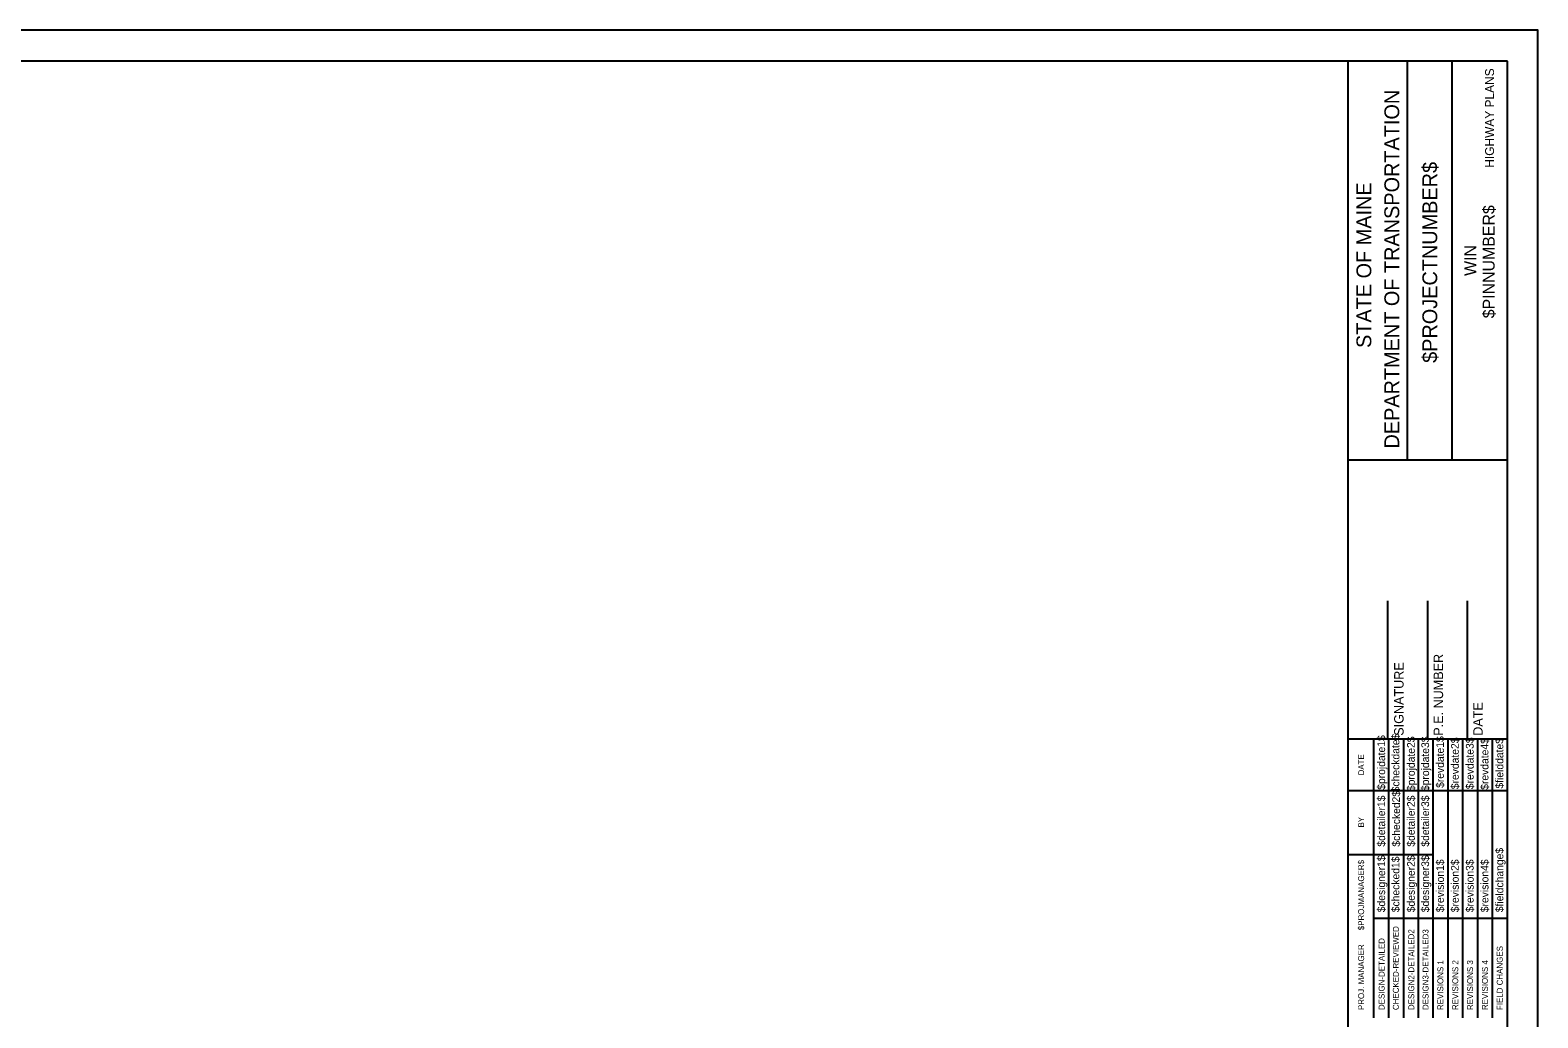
# Model space of a CAD drawing. Extents: x 850598 to 870284, y 366541 to 366651.
# Drawn here: x 857547.6 to 857642.3, y 366589.2 to 366651.2 of the extents above; entities that cross this region are included whole.
import ezdxf

# ---------------------------------------------------------------- set-up
doc = ezdxf.new("R2010")
doc.units = 0
for name, color, linetype in [('BORDER', 7, 'Continuous'), ('HIGHWAY_TITLE', 7, 'Continuous'), ('PLOT BOUNDARY', 7, 'Continuous')]:
    doc.layers.add(name, color=color, linetype=linetype)

msp = doc.modelspace()

# ---------------------------------------------------------------- linework, layer by layer
at = {"layer": 'BORDER'}
for p, q in [((857640.35, 366649.225), (857480.35, 366649.225)), ((857630.35, 366544.225), (857630.35, 366649.225)), ((857634.079, 366624.222), (857634.079, 366649.222)), ((857636.874, 366624.222), (857636.874, 366649.222)), ((857640.35, 366544.225), (857640.35, 366649.225)), ((857630.351, 366624.219), (857640.35, 366624.219)), ((857632.85, 366606.728), (857632.85, 366615.376)), ((857635.35, 366606.728), (857635.35, 366615.376)), ((857637.85, 366606.728), (857637.85, 366615.376)), ((857630.35, 366606.728), (857640.35, 366606.728))]:
    msp.add_line(p, q, dxfattribs=at)
for points in [[(857631.965, 366603.478), (857631.965, 366606.728)], [(857631.966, 366589.231), (857631.966, 366606.022)], [(857632.897, 366589.231), (857632.897, 366606.728)], [(857633.829, 366606.728), (857633.829, 366589.231)], [(857634.761, 366589.231), (857634.761, 366606.728)], [(857635.693, 366589.231), (857635.693, 366606.728)], [(857636.624, 366589.231), (857636.624, 366606.728)], [(857637.556, 366589.231), (857637.556, 366606.728)], [(857638.488, 366589.231), (857638.488, 366606.728)], [(857639.419, 366589.231), (857639.419, 366606.728)], [(857630.35, 366603.478), (857640.35, 366603.478)], [(857630.35, 366599.478), (857631.966, 366599.478)], [(857631.965, 366599.478), (857635.692, 366599.478)], [(857631.965, 366595.478), (857640.35, 366595.478)]]:
    msp.add_lwpolyline(points, dxfattribs=at)
at = {"layer": 'PLOT BOUNDARY'}
msp.add_lwpolyline([(857472.257, 366541.166), (857642.257, 366541.166), (857642.257, 366651.166), (857472.257, 366651.166)], close=True, dxfattribs=at)

# ---------------------------------------------------------------- texts
at = {"layer": 'BORDER'}
for s, height, p in [('DEPARTMENT OF TRANSPORTATION', 0.93176, (857633.557, 366624.931)), ('$PROJECTNUMBER$', 0.93176, (857635.942, 366630.304)), ('STATE OF MAINE', 0.93176, (857631.805, 366631.237)), ('$PINNUMBER$', 0.74527, (857639.546, 366633.1)), ('WIN', 0.7453, (857638.387, 366635.755)), ('SIGNATURE', 0.5906, (857633.83, 366606.92)), ('P.E. NUMBER', 0.59055, (857636.311, 366606.92)), ('DATE', 0.5906, (857638.791, 366606.92)), ('$projdate1$', 0.48455, (857632.673, 366603.529)), ('$checkdate$', 0.48455, (857633.567, 366603.371)), ('$projdate2$', 0.48455, (857634.536, 366603.45)), ('$projdate3$', 0.48455, (857635.431, 366603.45)), ('$revdate1$', 0.4845, (857636.362, 366603.647)), ('$revdate2$', 0.4845, (857637.294, 366603.568)), ('$revdate3$', 0.4845, (857638.226, 366603.568)), ('$revdate4$', 0.4845, (857639.157, 366603.529)), ('$fielddate$', 0.48455, (857640.089, 366603.607)), ('DATE', 0.3714, (857631.354, 366604.434)), ('$detailer1$', 0.48455, (857632.673, 366599.963)), ('$checked2$', 0.4845, (857633.605, 366599.963)), ('$detailer2$', 0.48455, (857634.536, 366599.963)), ('$detailer3$', 0.48455, (857635.431, 366599.963)), ('BY', 0.3714, (857631.354, 366601.163)), ('$designer1$', 0.48455, (857632.673, 366595.851)), ('$checked1$', 0.4845, (857633.567, 366595.851)), ('$designer2$', 0.48455, (857634.536, 366595.851)), ('$designer3$', 0.48455, (857635.431, 366595.851)), ('$fieldchange$', 0.48455, (857640.089, 366595.851)), ('$PROJMANAGER$', 0.37275, (857631.354, 366594.723)), ('$revision1$', 0.48455, (857636.362, 366595.851)), ('$revision2$', 0.48455, (857637.294, 366595.851)), ('$revision3$', 0.48455, (857638.226, 366595.851)), ('$revision4$', 0.48455, (857639.157, 366595.851)), ('CHECKED-REVIEWED', 0.37275, (857633.531, 366589.716)), ('DESIGN2-DETAILED2', 0.37275, (857634.5, 366589.716)), ('DESIGN3-DETAILED3', 0.37275, (857635.394, 366589.716)), ('PROJ. MANAGER', 0.37275, (857631.354, 366589.716)), ('DESIGN-DETAILED', 0.37275, (857632.637, 366589.716)), ('FIELD CHANGES', 0.37275, (857640.053, 366589.716)), ('REVISIONS 1', 0.37275, (857636.326, 366589.716)), ('REVISIONS 2', 0.37275, (857637.258, 366589.716)), ('REVISIONS 3', 0.37275, (857638.189, 366589.716)), ('REVISIONS 4', 0.37275, (857639.121, 366589.716))]:
    msp.add_text(s, height=height, rotation=90, dxfattribs=at).set_placement(p)
at = {"layer": 'HIGHWAY_TITLE'}
msp.add_text('HIGHWAY PLANS', height=0.55901, rotation=90, dxfattribs=at).set_placement((857639.508, 366642.541))

doc.saveas('drawing.dxf')
